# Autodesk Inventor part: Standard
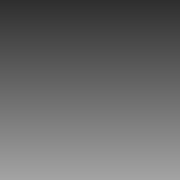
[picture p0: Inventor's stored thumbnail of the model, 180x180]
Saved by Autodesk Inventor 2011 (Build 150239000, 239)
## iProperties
Created: 2008-09
Part Number: Standard
Document SubType Name: Modeling
Designer: jim.clevenger
Density: 1 g/cm^3
Author: jim.clevenger
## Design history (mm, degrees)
node "Sketch1"
